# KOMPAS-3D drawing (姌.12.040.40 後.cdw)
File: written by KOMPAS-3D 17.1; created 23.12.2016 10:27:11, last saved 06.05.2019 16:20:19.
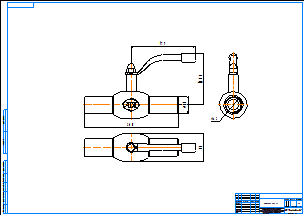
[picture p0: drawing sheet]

Sheet 1: A1, landscape

Title block, sheet 1: name: КШ.12.040.40 сс; material: Внимание! Данный продукт является объектом авторского права ООО «Торговый Дом АДЛ». / Запрещается изменение, копирование, распространение / (в том числе путем копирования на другие сайты и ресурсы в Интернете) / или любое иное использование информации и объектов без предварительного / согласия правообладателя (ООО «Торговый Дом АДЛ»).; sheets: 1; organisation: ООО "Торговый дом АДЛ"; sheet format: A1; stored path: C:\Users\tra\Desktop\2д чертежи\Шаровые краны БИВАЛ\КШ_Бивал_серия_11_12\KOMPAS_2D\КШ.12.040.40 сс.cdw

Views: Вид 1, Проекционный вид 2, Проекционный вид 3
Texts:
  Klimkovich
  ADL
Dimensions and other numbers on the sheet: 260; 48; 179; 142,6; 42; 76; 1:1; 1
